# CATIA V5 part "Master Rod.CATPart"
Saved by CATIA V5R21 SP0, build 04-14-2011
Part number: Master Rod
Bounding box of the stored display mesh (mm): x -55.99 to 55.99, y -51.999 to 267.322, z -35 to 35
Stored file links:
  D:\CATIA V5R21 E-RESOURCES\CATIA-V5R21\catia-v5r21-Prts\c13_catia_v5r21_prt\c13_catia_v5r21_figr_13-41\Part & Asm files\Master Rod.CATPart
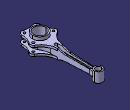
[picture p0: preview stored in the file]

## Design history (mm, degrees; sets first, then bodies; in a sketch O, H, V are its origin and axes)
Body1 (main body)
  Sketch1 on xy-plane, origin (0, 0, 0), H (1, 0, 0), V (0, 1, 0)
    arc A1 centre (0, 0) radius 31.5 from (-26.3425, 17.272) to (26.3425, 17.272) ccw
    arc A2 centre (0, 250) radius 17.5 from (14.7398, 240.5666) to (-14.7398, 240.5666) ccw
    point P1 (0, 250)
    line L1 (9, 220) -> (13, 60)
    point P2 (9, 220)
    point P3 (13, 60)
    arc A3 centre (94.6219, 62.0405) radius 81.6474 from (13, 60) to (26.3425, 17.272) ccw
    point P5 (26.3425, 17.272)
    arc A4 centre (45.4514, 220.9113) radius 36.4628 from (9, 220) to (14.7398, 240.5666) cw
    point P7 (14.7398, 240.5666)
    point P8 (-14.7398, 240.5666)
    point P9 (-9, 220)
    arc A5 centre (-45.4514, 220.9113) radius 36.4628 from (-9, 220) to (-14.7398, 240.5666) ccw
    point P11 (-13, 60)
    line L2 (-9, 220) -> (-13, 60)
    point P12 (-26.3425, 17.272)
    arc A6 centre (-94.6219, 62.0405) radius 81.6474 from (-13, 60) to (-26.3425, 17.272) cw
    radius A1 = 31.5
    radius A2 = 17.5
    distance P1 H = 250
    distance V P3 = 13
    distance P2 V = 9
    distance P1 P2 V = 30
    distance P3 P2 V = 160
    coincidence: P1 V
    tangency: A3 L1, A3 A1, A4 L1, A4 A2
    symmetry: P7 P8 V, P2 P9 V, A4 A5 V, P3 P11 V, L1 L2 V, P5 P12 V, A3 A6 V
  Pad1: profile Sketch1, direction (0, 0, 1), length 21, mirrored extent
  Sketch2 on face of Pad1, origin (0, 0, 21), H (1, 0, 0), V (0, 1, 0)
    point P1 (43, 16)
    point P2 (26, -39)
    arc A1 centre (43, 16) radius 13 from (53.3864, 8.1819) to (49.3111, 27.3653) ccw
    arc A2 centre (26, -39) radius 13 from (22.0235, -51.3769) to (38.9864, -38.4063) ccw
    reference projected line E1 (9, 220) -> (12.2872, 88.5122) from edge of Pad1
    arc A3 centre (84.2647, 90.3117) radius 72 from (49.3111, 27.3653) to (12.2872, 88.5122) cw
    point P5 (49.3111, 27.3653)
    point P6 (12.2872, 88.5122)
    arc A4 centre (110.9113, -35.118) radius 72 from (38.9864, -38.4063) to (53.3864, 8.1819) cw
    point P8 (38.9864, -38.4063)
    point P9 (53.3864, 8.1819)
    point P10 (-12.2872, 88.5122)
    point P11 (-49.3111, 27.3653)
    arc A5 centre (-84.2647, 90.3117) radius 72 from (-49.3111, 27.3653) to (-12.2872, 88.5122) ccw
    point P13 (-53.3864, 8.1819)
    arc A6 centre (-43, 16) radius 13 from (-53.3864, 8.1819) to (-49.3111, 27.3653) cw
    point P15 (-38.9864, -38.4063)
    arc A7 centre (-110.9113, -35.118) radius 72 from (-38.9864, -38.4063) to (-53.3864, 8.1819) ccw
    arc A8 centre (-26, -39) radius 13 from (-22.0235, -51.3769) to (-38.9864, -38.4063) cw
    line L1 (12.2872, 88.5122) -> (-12.2872, 88.5122)
    arc A9 centre (0, -119.9259) radius 72 from (-22.0235, -51.3769) to (22.0235, -51.3769) cw
    distance V P2 = 26
    distance P2 P1 H = 17
    distance P1 P2 V = 55
    distance P2 H = 39
    radius A1 = 13
    radius A2 = 13
    radius A3 = 72
    radius A4 = 72
    radius A9 = 72
    tangency: A3 E1, A3 A1, A4 A1, A4 A2, A9 A8, A9 A2
    symmetry: P6 P10 V, P5 P11 V, A3 A5 V, P9 P13 V, A1 A6 V, P8 P15 V, A4 A7 V, A2 A8 V
    horizontal: L1 H
  Pad2: profile Sketch2, direction (0, 0, -1), length 9
  Mirror1: of Pad2, Sketch2, about xy-plane
  Sketch3 on xy-plane, origin (0, 0, 0), H (1, 0, 0), V (0, 1, 0)
    circle A1 centre (0, 0) radius 31.5
    reference projected arc E1 centre (0, 0) radius 31.5 from (-26.3425, 17.272) to (26.3425, 17.272) ccw from edge of Pad2
    tangency: A1 E1
  Pad3: profile Sketch3, direction (0, 0, 1), length 35, mirrored extent
  Sketch4 on xy-plane, origin (0, 0, 0), H (1, 0, 0), V (0, 1, 0)
    circle A1 centre (0, 0) radius 26
    circle A2 centre (43, 16) radius 5
    circle A3 centre (26, -39) radius 5
    reference projected arc E1 centre (43, 16) radius 13 from (53.3864, 8.1819) to (49.3111, 27.3653) ccw from edge of Pad2
    reference projected arc E2 centre (26, -39) radius 13 from (22.0235, -51.3769) to (38.9864, -38.4063) ccw from edge of Pad2
    circle A4 centre (-26, -39) radius 5
    circle A5 centre (-43, 16) radius 5
    radius A1 = 26
    radius A3 = 5
    radius A2 = 5
    concentricity: A2 E1, A3 E2
    symmetry: A3 A4 V, A2 A5 V
  Pocket1: profile Sketch4, direction (0, 0, -1), length 35, mirrored extent
  Sketch5 on yz-plane, origin (0, 0, 0), H (0, 1, 0), V (0, 0, 1)
    line L1 (123.0834, 12) -> (250, 9)
    point P1 (123.0834, 12)
    point P2 (250, 9)
    arc A1 centre (124.9266, 89.9782) radius 78 from (88.5122, 21) to (123.0834, 12) ccw
    line L2 (88.5122, 21) -> (88.5122, 33.8539)
    line L3 (88.5122, 33.8539) -> (280.7471, 33.8539)
    line L4 (280.7471, 33.8539) -> (280.7471, 8.2732)
    point P8 (280.7471, 8.2732)
    line L5 (280.7471, 8.2732) -> (250, 9)
    distance P1 H = 12
    distance H P2 = 9
    distance V P2 = 250
    radius A1 = 78
    tangency: A1 L1, L5 A1
    vertical: L2 V, L4 V
    horizontal: L3 H
    coincidence: P8 L1
  Pocket2: profile Sketch5, direction (-1, 0, 0), length 35, mirrored extent
  Mirror2: of Pocket2, Sketch5, about xy-plane
  Sketch6 on xy-plane, origin (0, 0, 0), H (1, 0, 0), V (0, 1, 0)
    circle A1 centre (0, 250) radius 17.5
    point P1 (0, 250)
    reference projected arc E1 centre (0, 250) radius 17.5 from (17.5, 250) to (-17.5, 250) ccw from edge of Mirror2
    reference projected arc E2 centre (0, 250) radius 17.5 from (17.5, 250) to (-17.5, 250) ccw from edge of Mirror2
    coincidence: P1 V
    concentricity: E1 A1
    tangency: E2 A1
  Pad4: profile Sketch6, direction (0, 0, 1), length 21, mirrored extent
  Sketch7 on xy-plane, origin (0, 0, 0), H (1, 0, 0), V (0, 1, 0)
    circle A1 centre (0, 250) radius 12
    point P1 (0, 250)
    reference projected circle E1 centre (0, 250) radius 17.5 from edge of Pad4
    radius A1 = 12
    coincidence: P1 V
    concentricity: A1 E1
  Pocket3: profile Sketch7, direction (0, 0, -1), length 21, mirrored extent
  Sketch8 on xy-plane, origin (0, 0, 0), H (1, 0, 0), V (0, 1, 0)
    construction line L1 (0, 70) -> (0, 220)
    point P1 (0, 70)
    point P2 (0, 220)
    line L2 (-6, 70) -> (-6, 220)
    line L3 (6, 220) -> (6, 70)
    arc A1 centre (0, 220) radius 6 from (-6, 220) to (6, 220) cw
    arc A2 centre (0, 70) radius 6 from (6, 70) to (-6, 70) cw
    point P7 (0, 250)
    reference projected circle E1 centre (0, 250) radius 12 from edge of Pocket3
    length L1 = 150
    distance P7 P2 = 30
    radius A1 = 6
    coincidence: P1 V, P7 L1
    vertical: L1 V
    tangency: A1 L2, A2 L2, A1 L3, A2 L3
    parallelism: L1 L2
    concentricity: P7 E1
  Pocket4: profile Sketch8, direction (0, 0, 1), through (limit type 6), opposite side length -2.5
  Mirror3: of Pocket4, Sketch8, about xy-plane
